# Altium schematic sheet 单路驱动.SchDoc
size A4
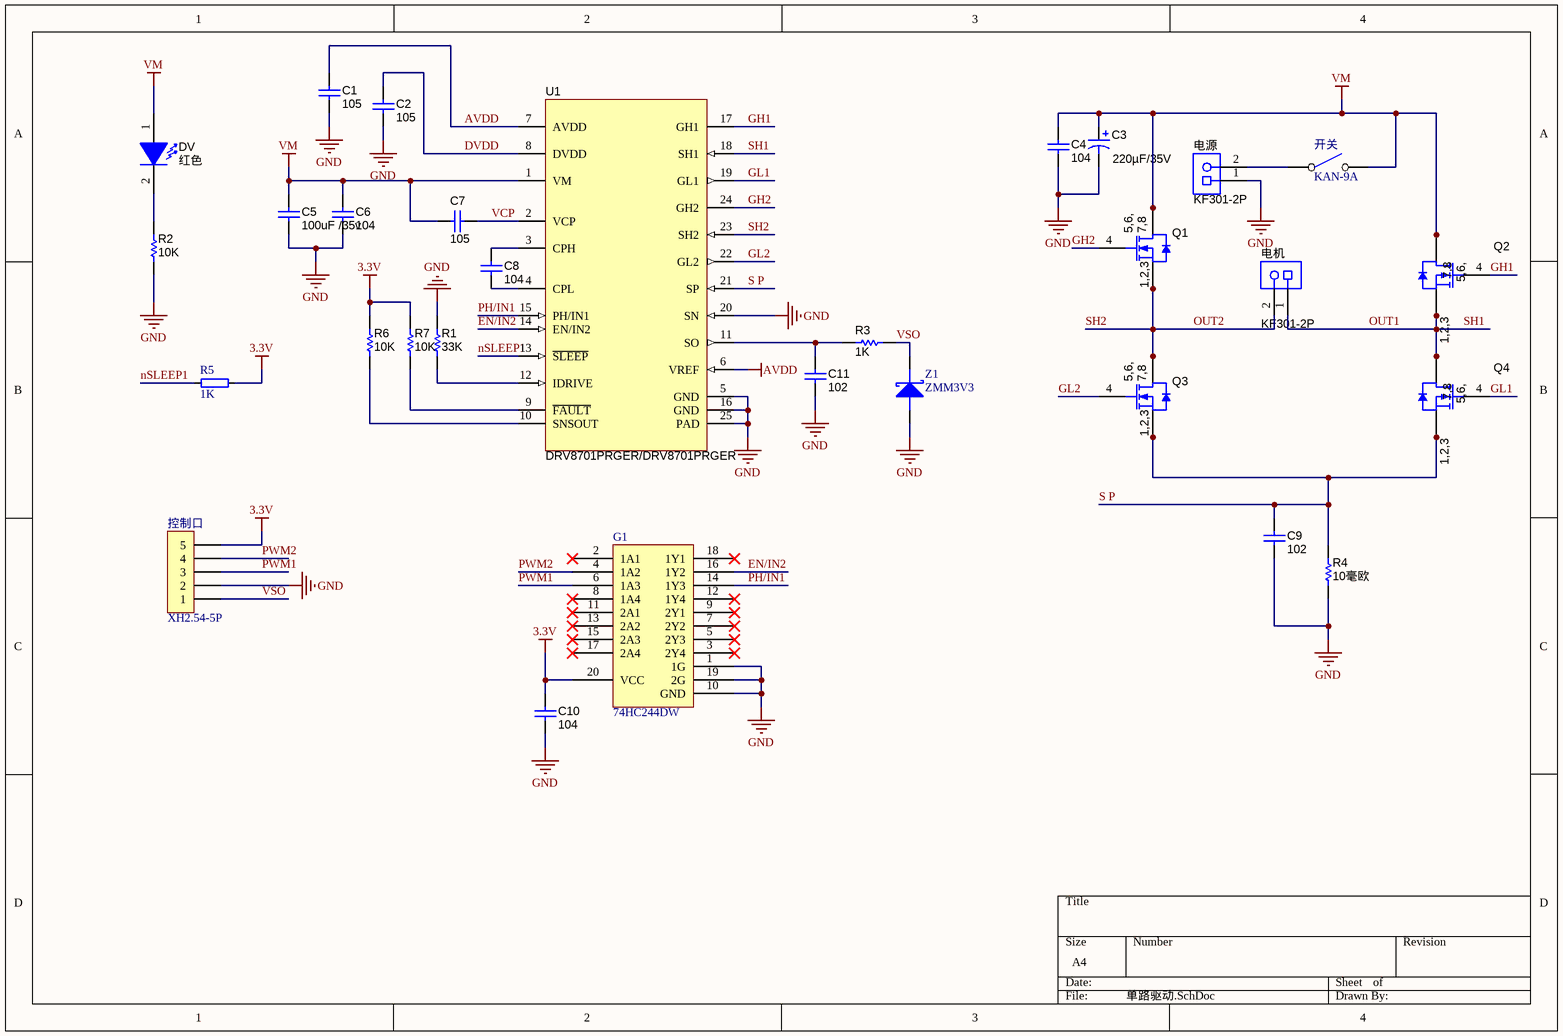
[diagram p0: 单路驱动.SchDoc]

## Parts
C1  105  [LQ_C0603]
C2  105  [LQ_C0603]
C3  220µF/35V  [LQ_C8X10]
C4  104  [LQ_C0603]
C5  100uF /35v  [LQ_C0603]
C6  104  [LQ_C0603]
C7  105  [LQ_C0603]
C8  104  [LQ_C0603]
C9  102  [LQ_C0603]
C10  104  [LQ_C0603]
C11  102  [LQ_C0603]
DV  红色  [LQ_LED0603R]
G1  74HC244DW  [LQ_TSSOP20S]
Q1  TPH1R403NL/CSD18532Q5B  [TRANS_NexFET_Q5B]  (value not drawn)
Q2  TPH1R403NL/CSD18532Q5B  [TRANS_NexFET_Q5B]  (value not drawn)
Q3  TPH1R403NL/CSD18532Q5B  [TRANS_NexFET_Q5B]  (value not drawn)
Q4  TPH1R403NL/CSD18532Q5B  [TRANS_NexFET_Q5B]  (value not drawn)
R1  33K  [LQ_R0603]
R2  10K  [LQ_R0603]
R3  1K  [LQ_R0603]
R4  10毫欧  [LQ_R2512]
R5  1K  [LQ_R0603]
R6  10K  [LQ_R0603]
R7  10K  [LQ_R0603]
U1  DRV8701PRGER/DRV8701PRGER  [RGE0024F]
Z1  ZMM3V3  [LQ_1206D]
开关  KAN-9A  [KFT DIP-7X7]
控制口  XH2.54-5P  [LQ_XH254-5PW]
电机  KF301-2P  [LQ_PIN2]
电源  KF301-2P  [LQ_PIN2]

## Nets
3.3V: C10.1 G1.20(VCC) R5.2 R6.2 R7.2 控制口.5
AVDD: C1.1 U1.6(VREF) U1.7(AVDD)
GND: C1.2 C2.2 C3.2(-) C4.2 C5.2 C6.2 C9.2 C10.2 C11.2 G1.1(1G) G1.10(GND) G1.19(2G) R1.2 R2.1 R4.1 U1.5(GND) U1.16(GND) U1.20(SN) U1.25(PAD) Z1.1 控制口.2 电源.1
VM: C3.1(+) C4.1 C5.1 C6.1 C7.1 DV.1(A) Q1.5(D) Q1.6(D) Q1.7(D) Q1.8(D) Q2.5(D) Q2.6(D) Q2.7(D) Q2.8(D) U1.1(VM) 开关.2(NO)
DVDD: C2.1 U1.8(DVDD)
EN/IN2: G1.16(1Y2) U1.14(EN/IN2)
GH1: Q2.4(G) U1.17(GH1)
GH2: Q1.4(G) U1.24(GH2)
GL1: Q4.4(G) U1.19(GL1)
GL2: Q3.4(G) U1.22(GL2)
nSLEEP1: R5.1 U1.13(~{SLEEP})
OUT1: Q2.1(S) Q2.2(S) Q2.3(S) Q4.5(D) Q4.6(D) Q4.7(D) Q4.8(D) U1.18(SH1) 电机.1  [also labelled SH1]
OUT2: Q1.1(S) Q1.2(S) Q1.3(S) Q3.5(D) Q3.6(D) Q3.7(D) Q3.8(D) U1.23(SH2) 电机.2  [also labelled SH2]
PH/IN1: G1.14(1Y3) U1.15(PH/IN1)
PWM1: G1.6(1A3) 控制口.3
PWM2: G1.4(1A2) 控制口.4
S P: C9.1 Q3.1(S) Q3.2(S) Q3.3(S) Q4.1(S) Q4.2(S) Q4.3(S) R4.2 U1.21(SP)
VCP: C7.2 U1.2(VCP)
VSO: R3.1 Z1.2 控制口.1
NetC8_1: C8.1 U1.3(CPH)
NetC8_2: C8.2 U1.4(CPL)
NetC11_1: C11.1 R3.2 U1.11(SO)
NetDV_2: DV.2(K) R2.2
NetR1_1: R1.1 U1.12(IDRIVE)
NetR6_1: R6.1 U1.10(SNSOUT)
NetR7_1: R7.1 U1.9(~{FAULT})
Net开关_1: 开关.1(COMMON) 电源.2

Not connected (* = marked no-connect by the designer): G1 2(1A1)* 3(2Y4)* 5(2Y3)* 7(2Y2)* 8(1A4)* 9(2Y1)* 11(2A1)* 12(1Y4)* 13(2A2)* 15(2A3)* 17(2A4)* 18(1Y1)*

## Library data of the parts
C1 C2 C4-C11 = C1608X7R1C105K: Manufacturer: TDK; Polarized: N; CompType: Capacitor; Value: 1uF; ValueDisplayed: 1µF; U/M: EA; Cap_F: 0.000001; Tolerance_%: 10; ESR_Ohm: 0.0057; Value1: 0.0057 ohm; VDC_V: 16; Value2: 16V; TempCo: X7R; TaMin_C: -55; TaMax_C: 125; Cap_Case: 0603
C3 = ECA-1HM471: Manufacturer: Panasonic; Polarized: Y; CompType: Capacitor; Value: 470uF; ValueDisplayed: 330µF/35V; U/M: EA; Cap_F: 0.00047; Tolerance_%: 20; Value1: Unknown; VDC_V: 50; Value2: 50V; IRMS_A: 0.65; TaMin_C: -40; TaMax_C: 85; Cap_Case: 10x20mm
DV = LTST-C171GKT: Manufacturer: Lite-On; CompType: LED; Value: Green; Vf_V: 2.1; Value2: 2.1V; Io_A: 20; Value1: W; U/M: EA
Q1-Q4 = CSD18532Q5B: Manufacturer: Texas Instruments; Alternate Manufacturer: None; CompType: MOSFET; U/M: EA; ChType: N; Value: 60V; VdsMax_V: 60; Value1: 3.3 ohm; Rdson45_Ohm: 3.3; Value2: 27 nC; QgTyp_nC: 27; Vgs_V: 1.6; IdsMax_A: 172
R1 R3 = CRCW06034K99FKEA: Manufacturer: Vishay-Dale; CompType: Resistor; Value: 10K; Res_ohm: 4990; Value_Code: 4k99; Tolerance_%: 1; Value1: 1%; Power_W: 0.1; Value2: 0.1W; VDC_V: 75; TempCo: 100 ppm/C; EIA_Code: E96; U/M: EA
R2 R6 R7 = CRCW06034K99FKEA: Manufacturer: Vishay-Dale; CompType: Resistor; Res_ohm: 4990; Value_Code: 4k99; Tolerance_%: 1; Value1: 1%; Power_W: 0.1; Value2: 0.1W; VDC_V: 75; TempCo: 100 ppm/C; EIA_Code: E96; U/M: EA
R4 = CRA2512-FZ-R010ELF: Manufacturer: Bourns; CompType: Resistor; Value: 0.01; Value_Code: R010; Tolerance_%: 1; Value1: 1%; Power_W: 3; Value2: 3W; TempCo: 75 ppm/C; EIA_Code: E96; U/M: EA
R5 = RES
U1 = DRV8701ERGER: Alternate PartNumber: DRV8701ERGET; Manufacturer: Texas Instruments; SymbolCreator: Altium; CompType: IC; U/M: EA
Z1 = LQ_D: Schottky Diode
开关 = SW SPST
控制口 = CON5: Connector
电机 电源 = 691 101 710 002: Manufacturer: Wurth Elektronik eiSos; SymbolCreator: a0412235; CompType: Terminal Block; U/M: EA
